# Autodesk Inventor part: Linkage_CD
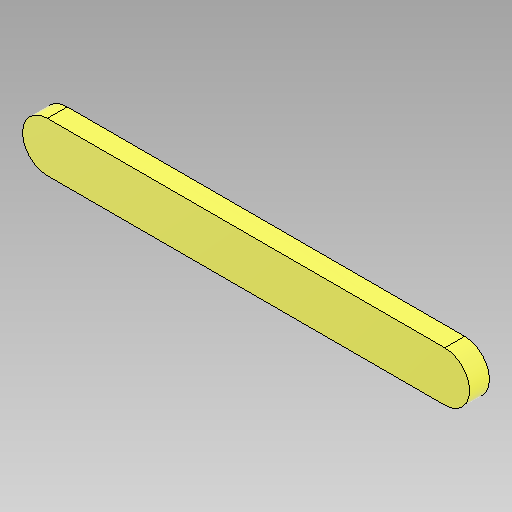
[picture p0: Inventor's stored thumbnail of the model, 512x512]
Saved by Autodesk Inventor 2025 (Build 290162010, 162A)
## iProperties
Created: 2024-10
Part Number: Linkage_CD
Material: Generic
Document SubType Name: Modeling
Designer: Dennis
Density: 1 g/cm^3
Appearance: Smooth - Yellow
Mass: 0.43927 g
Surface Area: 6.30686 cm^2
Volume: 0.43927 cm^3
Author: Dennis
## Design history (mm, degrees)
sketch "Sketch1"
  geometry: L1 (0, 0)-(40, 0); L2 (0, -2.5)-(40, -2.5); L3 (40, 2.5)-(0, 2.5); A1 r 2.5 centre (0, 0) between (0, 2.5) and (0, -2.5); A2 r 2.5 centre (40, 0) between (40, -2.5) and (40, 2.5); 1 further point
  constraints: 8 end point, 4 point on circle, 4 tangent, 2 centre point, 1 horizontal, 1 midpoint, 1 parallel
  dimensions: "d0" = 5 distance between parallel lines of L2 L3 (= w_); "d1" = 40 distance of L1.start L1.end (= CD_)
extrude "Extrusion1" new body sketch "Sketch1" stored distance "d2" = 2 (= t_); taper "d3" = 0 deg
body "Solid1"
other parameters: "CD_" = 40 [user parameter; used in 1 equation term], "w_" = 5 [user parameter; used in 1 equation term], "t_" = 2 [user parameter; used in 1 equation term]
